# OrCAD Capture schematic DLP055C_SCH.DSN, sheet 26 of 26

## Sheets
26 P05 - DLPC FPDlink/Parallel ln: size A3
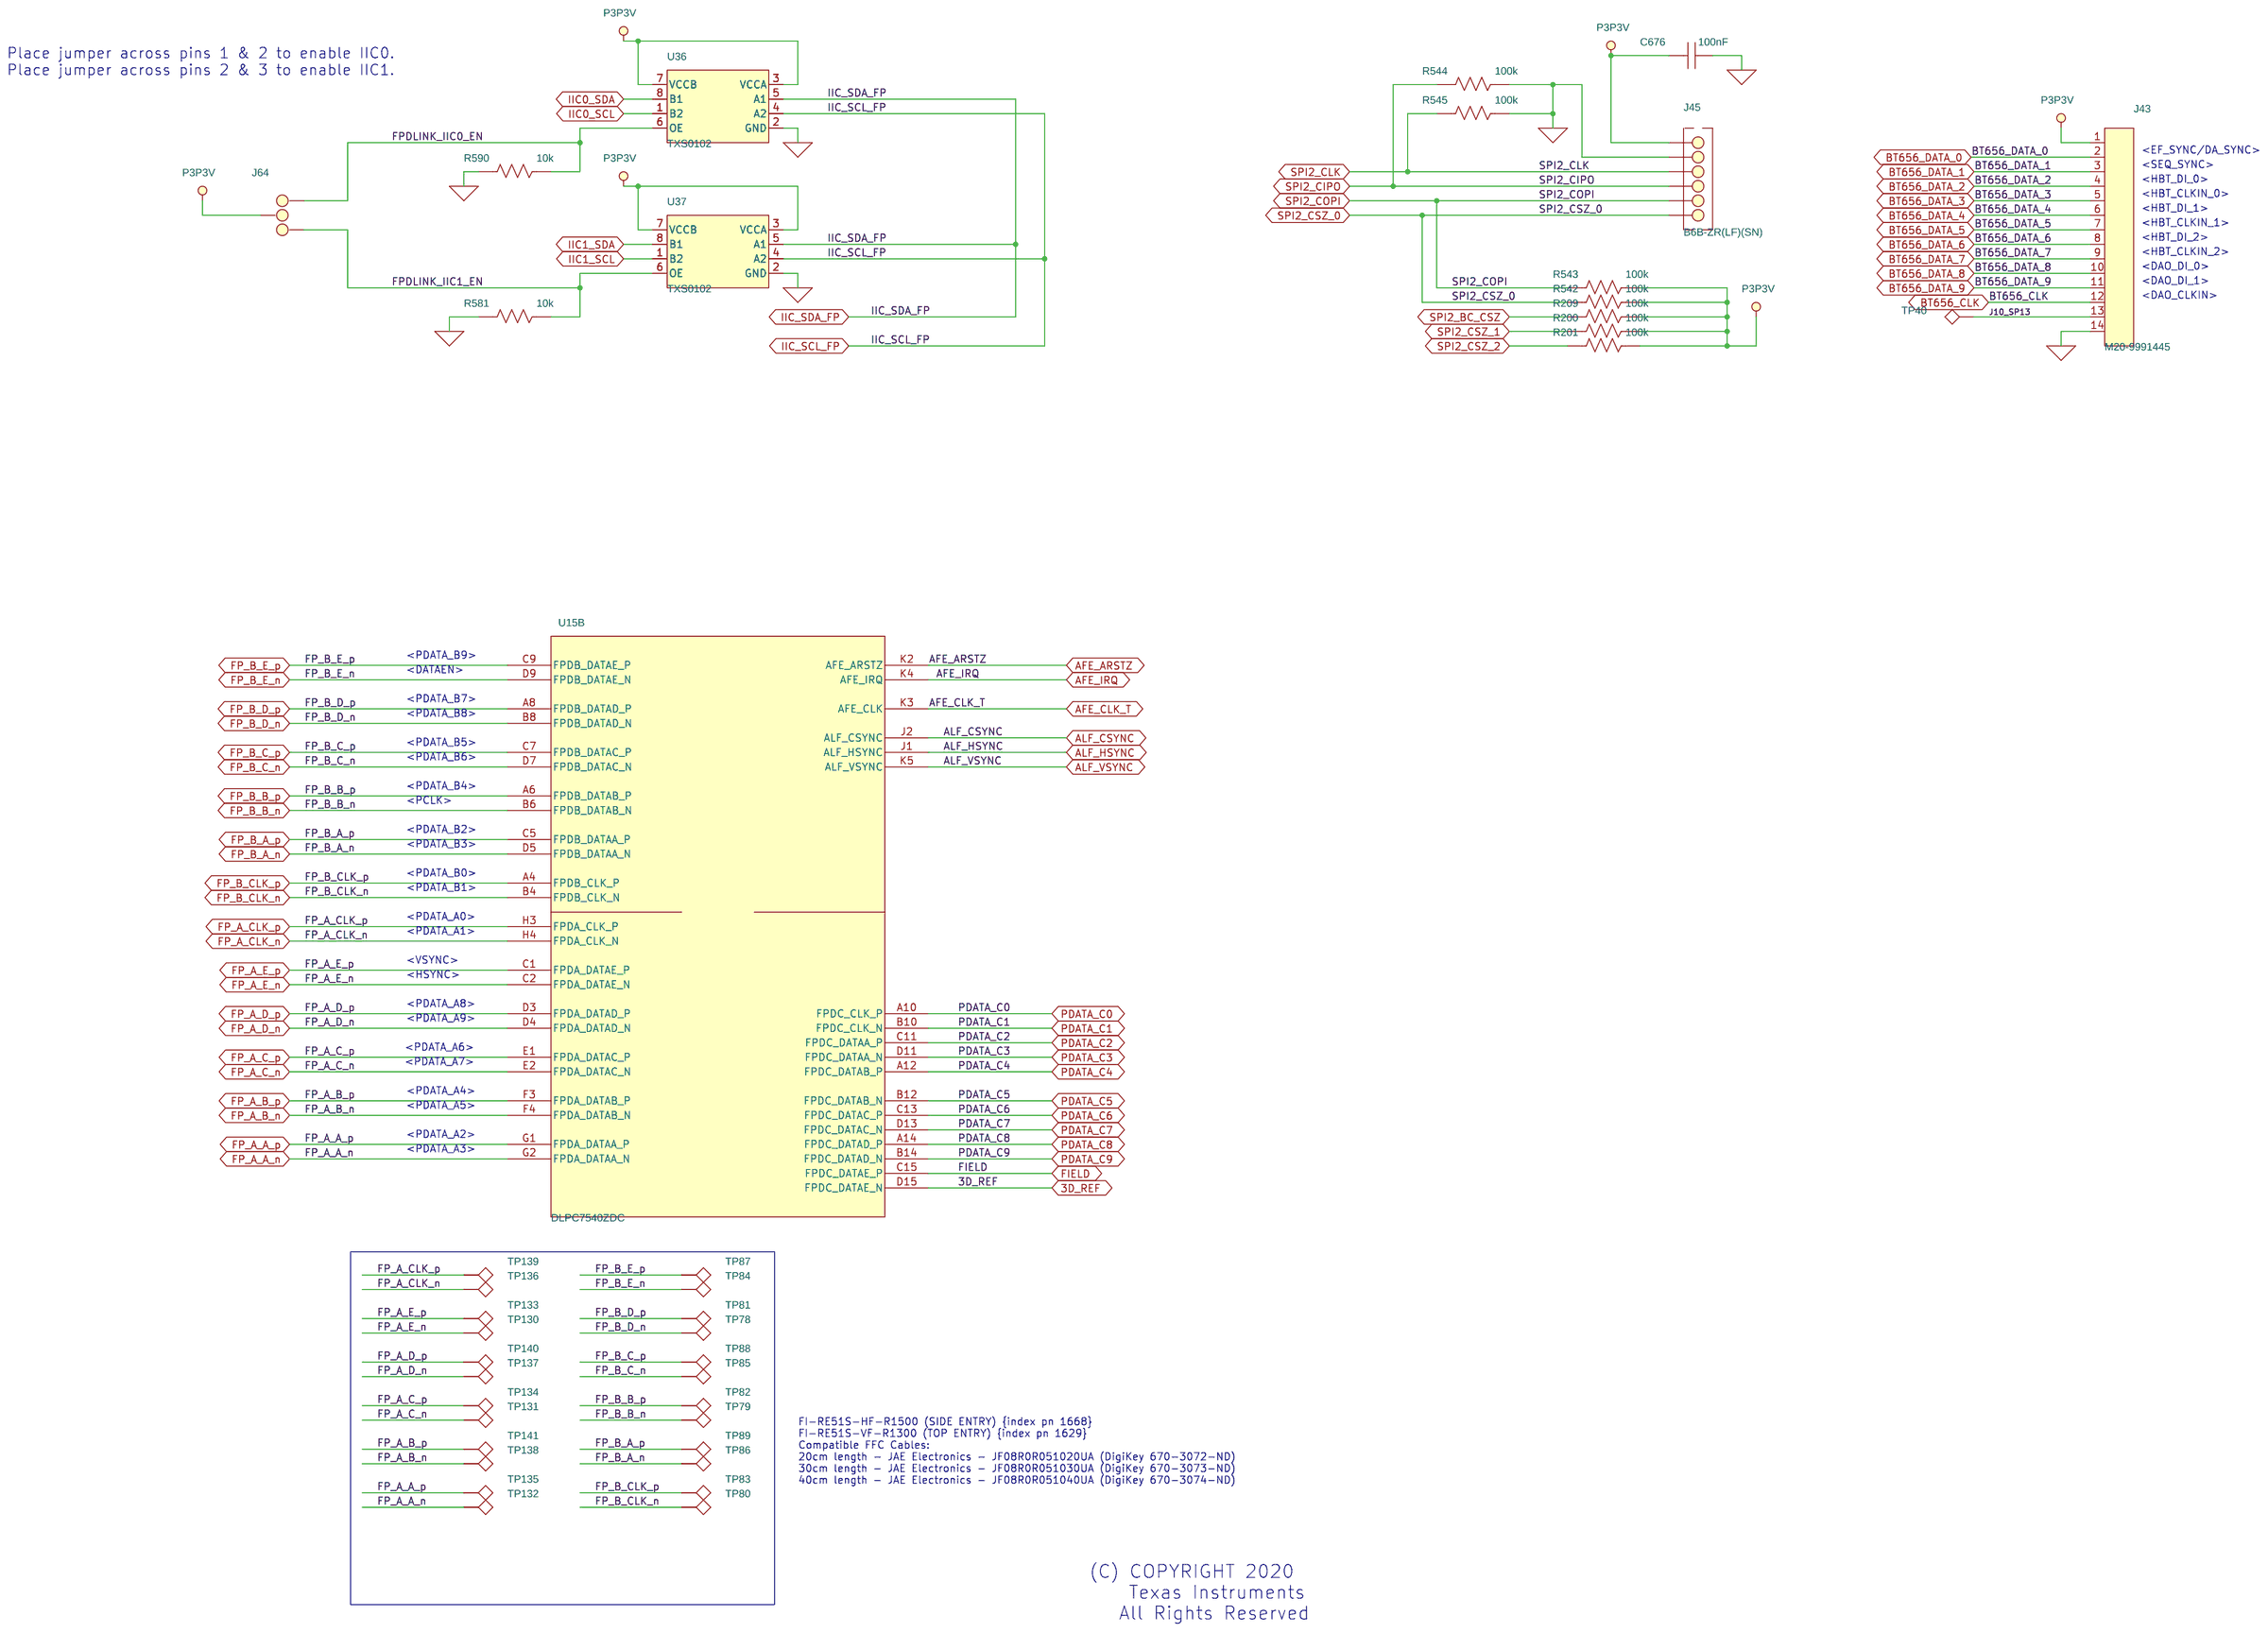
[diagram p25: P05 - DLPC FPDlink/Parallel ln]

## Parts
sheet P05 - DLPC FPDlink/Parallel ln
C676  100nF  [0402]
J43  HDR,14P,1R  [HDR1X14]
J45  B6B-ZR  [HDR1X6-B6B-ZR_JST]
J64  HDR,3P,1R  [HDR1X3]
R200  100k  [0402]
R201  100k  [0402]
R209  100k  [0402]
R542  100k  [0402]
R543  100k  [0402]
R544  100k  [0402]
R545  100k  [0402]
R581  10k  [0402]
R590  10k  [0402]
TP40  TP,28mil Drill,48mil Pad  [HTP-48RD28]
TP78  TP,20mil PAD  [20mil_PAD]
TP79  TP,20mil PAD  [20mil_PAD]
TP80  TP,20mil PAD  [20mil_PAD]
TP81  TP,20mil PAD  [20mil_PAD]
TP82  TP,20mil PAD  [20mil_PAD]
TP83  TP,20mil PAD  [20mil_PAD]
TP84  TP,20mil PAD  [20mil_PAD]
TP85  TP,20mil PAD  [20mil_PAD]
TP86  TP,20mil PAD  [20mil_PAD]
TP87  TP,20mil PAD  [20mil_PAD]
TP88  TP,20mil PAD  [20mil_PAD]
TP89  TP,20mil PAD  [20mil_PAD]
TP130  TP,20mil PAD  [20mil_PAD]
TP131  TP,20mil PAD  [20mil_PAD]
TP132  TP,20mil PAD  [20mil_PAD]
TP133  TP,20mil PAD  [20mil_PAD]
TP134  TP,20mil PAD  [20mil_PAD]
TP135  TP,20mil PAD  [20mil_PAD]
TP136  TP,20mil PAD  [20mil_PAD]
TP137  TP,20mil PAD  [20mil_PAD]
TP138  TP,20mil PAD  [20mil_PAD]
TP139  TP,20mil PAD  [20mil_PAD]
TP140  TP,20mil PAD  [20mil_PAD]
TP141  TP,20mil PAD  [20mil_PAD]
U36  TXS0102  [VSSOP-8_DCU]
U37  TXS0102  [VSSOP-8_DCU]
sheet P09 - DLPC GPIO
U15  TIDLP,DLPC7540  [DLPC7540_HBGA676_3131]  (sections A,B,C,D,E,F,G,H,I)

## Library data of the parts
C676 = PAS,CAP,NP: ALT_SYMBOLS: 0402_1mm; CCA: 5; DigiKey: 587-3499-1-ND; Family: passive; Index PN: 1280; Install: Y; Lead Style: SMT; MFG: Taiyo Yuden; Material: x5r; P/D_NUM: UMK105BJ104KV-F; Part Number: UMK105BJ104KV-F; Part Specific: CAP CER 0.1UF 50V 10% X5R 0402; TOLERANCE: 10%; Type: capacitor; VPC: 50V; Vendor: Taiyo Yuden
J43 = EM,HDR,14P,1R: DigiKey: M20-9991445-ND; Family: electro/mechanical; Index PN: 144; Install: Y; Lead Style: TH; MFG: Harwin; P/D_NUM: M20-9991445; Part Number: M20-9991445; Part Specific: CONN HEADER VERT 14POS 2.54MM; Pin Cnt: 14; Pin Spacing: 100mil; Row Cnt: 1; Type: header; Vendor: Harwin
J45 = EM,HDR,6P,1R,1x,B6B-EH: DigiKey: 455-1661-ND; Family: electro/mechanical; Index PN: 1663; Lead Style: TH; MFG: JST; P/D_NUM: B6B-ZR(LF)(SN); Part Number: B6B-ZR(LF)(SN); Part Specific: CONN HEADER VERT 6POS 1.5MM; Pin Cnt: 6; Pin Spacing: 1.5mm; Row Cnt: 1; Type: header; Vendor: JST
J64 = EM,JMP,3P,1R,1X,ALT: DigiKey: 952-2263-ND; Index PN: 20; Lead Style: TH; MFG: Harwin; P/D_NUM: M20-9990345; Part Number: M20-9990345; Part Specific: 3 Positions Header  Unshrouded  Breakaway Connector 0.100in (2.54mm) Through Hole Gold; Pin Cnt: 3; Pin Spacing: 100mil; Row Cnt: 1; Type: header; Vendor: Harwin
R200 R201 R209 R542-R545 = PAS,R,large: ALT_SYMBOLS: 0402_1mm; DigiKey: 541-100KLCT-ND; Family: passive; Index PN: 712; Lead Style: SMT; MFG: Vishay/Dale; Material: chip; P/D_NUM: CRCW0402100KFKED; Part Number: CRCW0402100KFKED; Part Specific: RES 100K OHM 1/10W 1% 0402 SMD; Power: 1/16W; Tolerance: 1%; Type: resistor; VPC: 1/16W; Vendor: Vishay/Dale
R581 R590 = PAS,R,large: ALT_SYMBOLS: 0402_1mm; DigiKey: 311-10.0KLRCT-ND; Family: passive; Index PN: 680; Lead Style: SMT; MFG: Yageo; Material: chip; P/D_NUM: RC0402FR-0710KL; Part Number: RC0402FR-0710KL; Power: 1/16W; Tolerance: 1%; Type: resistor; VPC: 1/16W; Vendor: Yageo
TP40 = EM,TERM,TESTPOINT: DigiKey: ---; Family: board feature; Index PN: 1498; Install: DNI; Lead Style: TH; MFG: -- NOT A PART --; Part Specific: HOLE PLATED 48mil pad 28mil drill; Type: hole,plated; Vendor: -- NOT A PART --
TP78-TP89 TP130-TP141 = EM,TERM,TESTPOINT: Family: board feature; Index PN: 1145; Install: DNI; Lead Style: SMT; MFG: -- NOT A PART --; Type: pad pattern; Vendor: -- NOT A PART --
U36 U37 = INF,DRVR,I2C,TXS0102,1x: DigiKey: 296-21931-1-ND; Family: interface; Index PN: 877; Lead Style: SMT; MFG: Texas Instruments; P/D_NUM: TXS0102DCU; Part Number: TXS0102DCU; Part Specific: IC VOLT-LEVEL TRANSLATOR 8-US8; Type: driver; Vendor: Texas Instruments
U15 = TIDLP,DLPC7540: MFG: Texas Instruments; Part Number: DLPC7540ZDC

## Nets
GND: C676.1 J43.14 J45.2 R544.2(N2) R545.2(N2) R581.1(N1) R590.1(N1) U36.2(GND) U37.2(GND) ; also on sheet 3 4 5 6 7 8 9 10 11 12 15 16 17 18 19 20 21 22 23 25
3D_REF: U15.D15(FPDC_DATAE_N) ; also on sheet 3
AFE_ARSTZ: U15.K2(AFE_ARSTZ) ; also on sheet 3
AFE_CLK_T: U15.K3(AFE_CLK) ; also on sheet 3
AFE_IRQ: U15.K4(AFE_IRQ) ; also on sheet 3
ALF_CSYNC: U15.J2(ALF_CSYNC) ; also on sheet 3
ALF_HSYNC: U15.J1(ALF_HSYNC) ; also on sheet 3
ALF_VSYNC: U15.K5(ALF_VSYNC) ; also on sheet 3
BT656_CLK: J43.12 ; also on sheet 3 20
BT656_DATA_0: J43.2 ; also on sheet 3 20
BT656_DATA_1: J43.3 ; also on sheet 3 20
BT656_DATA_2: J43.4 ; also on sheet 3 20
BT656_DATA_3: J43.5 ; also on sheet 3 20
BT656_DATA_4: J43.6 ; also on sheet 3 20
BT656_DATA_5: J43.7 ; also on sheet 3 20
BT656_DATA_6: J43.8 ; also on sheet 3 20
BT656_DATA_7: J43.9 ; also on sheet 3 20
BT656_DATA_8: J43.10 ; also on sheet 3 20
BT656_DATA_9: J43.11 ; also on sheet 3 20
FIELD: U15.C15(FPDC_DATAE_P) ; also on sheet 3
FP_A_A_n: TP132.1(P1) U15.G2(FPDA_DATAA_N) ; also on sheet 3
FP_A_A_p: TP135.1(P1) U15.G1(FPDA_DATAA_P) ; also on sheet 3
FP_A_B_n: TP138.1(P1) U15.F4(FPDA_DATAB_N) ; also on sheet 3
FP_A_B_p: TP141.1(P1) U15.F3(FPDA_DATAB_P) ; also on sheet 3
FP_A_C_n: TP131.1(P1) U15.E2(FPDA_DATAC_N) ; also on sheet 3
FP_A_C_p: TP134.1(P1) U15.E1(FPDA_DATAC_P) ; also on sheet 3
FP_A_CLK_n: TP136.1(P1) U15.H4(FPDA_CLK_N) ; also on sheet 3
FP_A_CLK_p: TP139.1(P1) U15.H3(FPDA_CLK_P) ; also on sheet 3
FP_A_D_n: TP137.1(P1) U15.D4(FPDA_DATAD_N) ; also on sheet 3
FP_A_D_p: TP140.1(P1) U15.D3(FPDA_DATAD_P) ; also on sheet 3
FP_A_E_n: TP130.1(P1) U15.C2(FPDA_DATAE_N) ; also on sheet 3
FP_A_E_p: TP133.1(P1) U15.C1(FPDA_DATAE_P) ; also on sheet 3
FP_B_A_n: TP86.1(P1) U15.D5(FPDB_DATAA_N) ; also on sheet 3
FP_B_A_p: TP89.1(P1) U15.C5(FPDB_DATAA_P) ; also on sheet 3
FP_B_B_n: TP79.1(P1) U15.B6(FPDB_DATAB_N) ; also on sheet 3
FP_B_B_p: TP82.1(P1) U15.A6(FPDB_DATAB_P) ; also on sheet 3
FP_B_C_n: TP85.1(P1) U15.D7(FPDB_DATAC_N) ; also on sheet 3
FP_B_C_p: TP88.1(P1) U15.C7(FPDB_DATAC_P) ; also on sheet 3
FP_B_CLK_n: TP80.1(P1) U15.B4(FPDB_CLK_N) ; also on sheet 3
FP_B_CLK_p: TP83.1(P1) U15.A4(FPDB_CLK_P) ; also on sheet 3
FP_B_D_n: TP78.1(P1) U15.B8(FPDB_DATAD_N) ; also on sheet 3
FP_B_D_p: TP81.1(P1) U15.A8(FPDB_DATAD_P) ; also on sheet 3
FP_B_E_n: TP84.1(P1) U15.D9(FPDB_DATAE_N) ; also on sheet 3
FP_B_E_p: TP87.1(P1) U15.C9(FPDB_DATAE_P) ; also on sheet 3
FPDLINK_IIC0_EN: J64.1 R590.2(N2) U36.6(OE)
FPDLINK_IIC1_EN: J64.3 R581.2(N2) U37.6(OE)
IIC0_SCL: U36.1(B2) ; also on sheet 4 5 15 18 19
IIC0_SDA: U36.8(B1) ; also on sheet 4 5 15 18 19
IIC1_SCL: U37.1(B2) ; also on sheet 15 19 20
IIC1_SDA: U37.8(B1) ; also on sheet 15 19 20
IIC_SCL_FP: U36.4(A2) U37.4(A2) ; also on sheet 3
IIC_SDA_FP: U36.5(A1) U37.5(A1) ; also on sheet 3
J10_SP13: J43.13 TP40.1(P1)
P3P3V: C676.2 J43.1 J45.1 J64.2 R200.2(N2) R201.2(N2) R209.2(N2) R542.2(N2) R543.2(N2) U36.3(VCCA) U36.7(VCCB) U37.3(VCCA) U37.7(VCCB) ; also on sheet 4 6 7 8 9 10 11 12 15 16 18 19 20 21 22 25
PDATA_C0: U15.A10(FPDC_CLK_P) ; also on sheet 3
PDATA_C1: U15.B10(FPDC_CLK_N) ; also on sheet 3
PDATA_C2: U15.C11(FPDC_DATAA_P) ; also on sheet 3
PDATA_C3: U15.D11(FPDC_DATAA_N) ; also on sheet 3
PDATA_C4: U15.A12(FPDC_DATAB_P) ; also on sheet 3
PDATA_C5: U15.B12(FPDC_DATAB_N) ; also on sheet 3
PDATA_C6: U15.C13(FPDC_DATAC_P) ; also on sheet 3
PDATA_C7: U15.D13(FPDC_DATAC_N) ; also on sheet 3
PDATA_C8: U15.A14(FPDC_DATAD_P) ; also on sheet 3
PDATA_C9: U15.B14(FPDC_DATAD_N) ; also on sheet 3
SPI2_BC_CSZ: R209.1(N1) ; also on sheet 20
SPI2_CIPO: J45.4 R544.1(N1) ; also on sheet 3 20
SPI2_CLK: J45.3 R545.1(N1) ; also on sheet 3 20
SPI2_COPI: J45.5 R543.1(N1) ; also on sheet 3 20
SPI2_CSZ_0: J45.6 R542.1(N1) ; also on sheet 3 20
SPI2_CSZ_1: R200.1(N1) ; also on sheet 3 20
SPI2_CSZ_2: R201.1(N1) ; also on sheet 3 20

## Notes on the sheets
sheet 26
- Place jumper across pins 1 & 2 to enable IIC0.
  Place jumper across pins 2 & 3 to enable IIC1.
- <EF_SYNC/DA_SYNC>
- <SEQ_SYNC>
- <HBT_CLKIN_0>
- <HBT_DI_0>
- <HBT_DI_1>
- <HBT_CLKIN_1>
- <HBT_DI_2>
- <HBT_CLKIN_2>
- <DAO_DI_0>
- <DAO_CLKIN>
- <DAO_DI_1>
- <PDATA_B9>
- <DATAEN>
- <PDATA_B7>
- <PDATA_B8>
- <PDATA_B5>
- <PDATA_B6>
- <PDATA_B4>
- <PCLK>
- <PDATA_B2>
- <PDATA_B3>
- <PDATA_B0>
- <PDATA_B1>
- <PDATA_A0>
- <PDATA_A1>
- <VSYNC>
- <HSYNC>
- <PDATA_A8>
- <PDATA_A9>
- <PDATA_A6>
- <PDATA_A7>
- <PDATA_A4>
- <PDATA_A5>
- <PDATA_A2>
- <PDATA_A3>
- FI-RE51S-HF-R1500 (SIDE ENTRY) {index pn 1668}
  FI-RE51S-VF-R1300 (TOP ENTRY) {index pn 1629}
  Compatible FFC Cables:
  20cm length - JAE Electronics - JF08R0R051020UA (DigiKey 670-3072-ND)
  30cm length - JAE Electronics - JF08R0R051030UA (DigiKey 670-3073-ND)
  40cm length - JAE Electronics - JF08R0R051040UA (DigiKey 670-3074-ND)
- (C) COPYRIGHT 2020
         Texas Instruments
        All Rights Reserved
